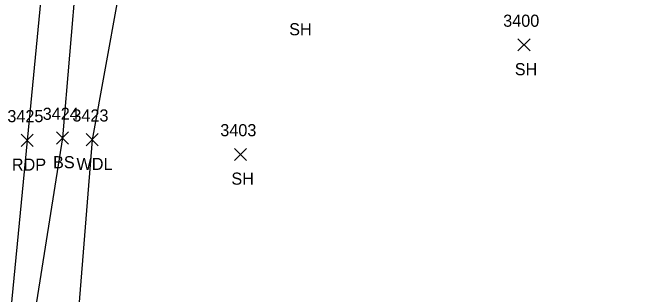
# Model space of a CAD drawing. Extents: x 1678863 to 1683592, y 407783 to 418211.
# Drawn here: x 1680401.7 to 1680506.9, y 414733.3 to 414779.8 of the extents above; entities that cross this region are included whole.
import ezdxf

# ---------------------------------------------------------------- set-up
doc = ezdxf.new("R2010")
doc.units = 0
for name, color, linetype in [('L_A', 7, 'Continuous'), ('L_I', 7, 'Continuous'), ('L_TIC', 7, 'Continuous'), ('LAWA', 7, 'Continuous'), ('LELB', 7, 'Continuous'), ('P_A', 7, 'Continuous'), ('P_I', 7, 'Continuous'), ('P_TIC', 7, 'Continuous'), ('PET', 7, 'Continuous')]:
    doc.layers.add(name, color=color, linetype=linetype)

msp = doc.modelspace()

# ---------------------------------------------------------------- linework, layer by layer
at = {"layer": 'L_TIC'}
for points in [[(1680484.95, 414773.45), (1680486.95, 414775.45)], [(1680486.95, 414773.45), (1680484.95, 414775.45)], [(1680408.85, 414758.09), (1680410.85, 414760.09)], [(1680410.85, 414758.09), (1680408.85, 414760.09)], [(1680413.74, 414757.81), (1680415.74, 414759.81)], [(1680415.74, 414757.81), (1680413.74, 414759.81)], [(1680438.21, 414755.38), (1680440.21, 414757.38)], [(1680440.21, 414755.38), (1680438.21, 414757.38)]]:
    msp.add_lwpolyline(points, dxfattribs=at)
at = {"layer": 'LAWA'}
msp.add_lwpolyline([(1680631.22, 414748.81), (1680599.57, 414760.95), (1680549.03, 414780.72), (1680516.79, 414791.82), (1680486.46, 414799.02), (1680463.26, 414805.73), (1680421.05, 414793.75), (1680414.74, 414758.81), (1680411.4, 414716.9), (1680407.3, 414688.75), (1680403.02, 414676.63), (1680402.83, 414664.98), (1680404.53, 414653.79)], dxfattribs=at)
at = {"layer": 'LELB'}
msp.add_lwpolyline([(1680412.63, 414818.89), (1680415.09, 414806.01), (1680412.16, 414786.48), (1680409.85, 414759.09), (1680404.3, 414724.04), (1680399.02, 414676), (1680399.71, 414653.6), (1680402.32, 414653.35)], dxfattribs=at)
at = {"layer": 'P_TIC'}
for points in [[(1680403.02, 414757.7), (1680405.02, 414759.7)], [(1680405.02, 414757.7), (1680403.02, 414759.7)]]:
    msp.add_lwpolyline(points, dxfattribs=at)
at = {"layer": 'PET'}
msp.add_lwpolyline([(1680495.8, 415211.55), (1680487.74, 415180.8), (1680478.66, 415148.16), (1680471.94, 415120.07), (1680462.57, 415079.59), (1680454.69, 415044.69), (1680445.65, 415004.54), (1680436.54, 414962.49), (1680430.18, 414933.71), (1680423.61, 414897.47), (1680418.44, 414869.8), (1680415.44, 414847.01), (1680410.82, 414817.35), (1680406.85, 414787.83), (1680404.02, 414758.7), (1680400.52, 414722.33), (1680395.79, 414677.26), (1680393.31, 414652.78), (1680390.17, 414616.43), (1680385.57, 414569.94), (1680383.24, 414550.06), (1680381.08, 414523.52), (1680377.37, 414484.42)], dxfattribs=at)

# ---------------------------------------------------------------- texts
at = {"layer": 'L_A'}
for s, p in [('SH', (1680447.23, 414776.04)), ('SH', (1680484.43, 414769.45)), ('BS', (1680408.29, 414754.09)), ('WDL', (1680412.16, 414753.81)), ('SH', (1680437.7, 414751.38))]:
    msp.add_text(s, height=2, dxfattribs=at).set_placement(p)
at = {"layer": 'L_I'}
for s, p in [('3400', (1680482.52, 414777.45)), ('3424', (1680406.59, 414762.09)), ('3423', (1680411.48, 414761.81)), ('3403', (1680435.87, 414759.38))]:
    msp.add_text(s, height=2, dxfattribs=at).set_placement(p)
at = {"layer": 'P_A'}
msp.add_text('RDP', height=2, dxfattribs=at).set_placement((1680401.5, 414753.7))
at = {"layer": 'P_I'}
msp.add_text('3425', height=2, dxfattribs=at).set_placement((1680400.76, 414761.7))

doc.saveas('drawing.dxf')
